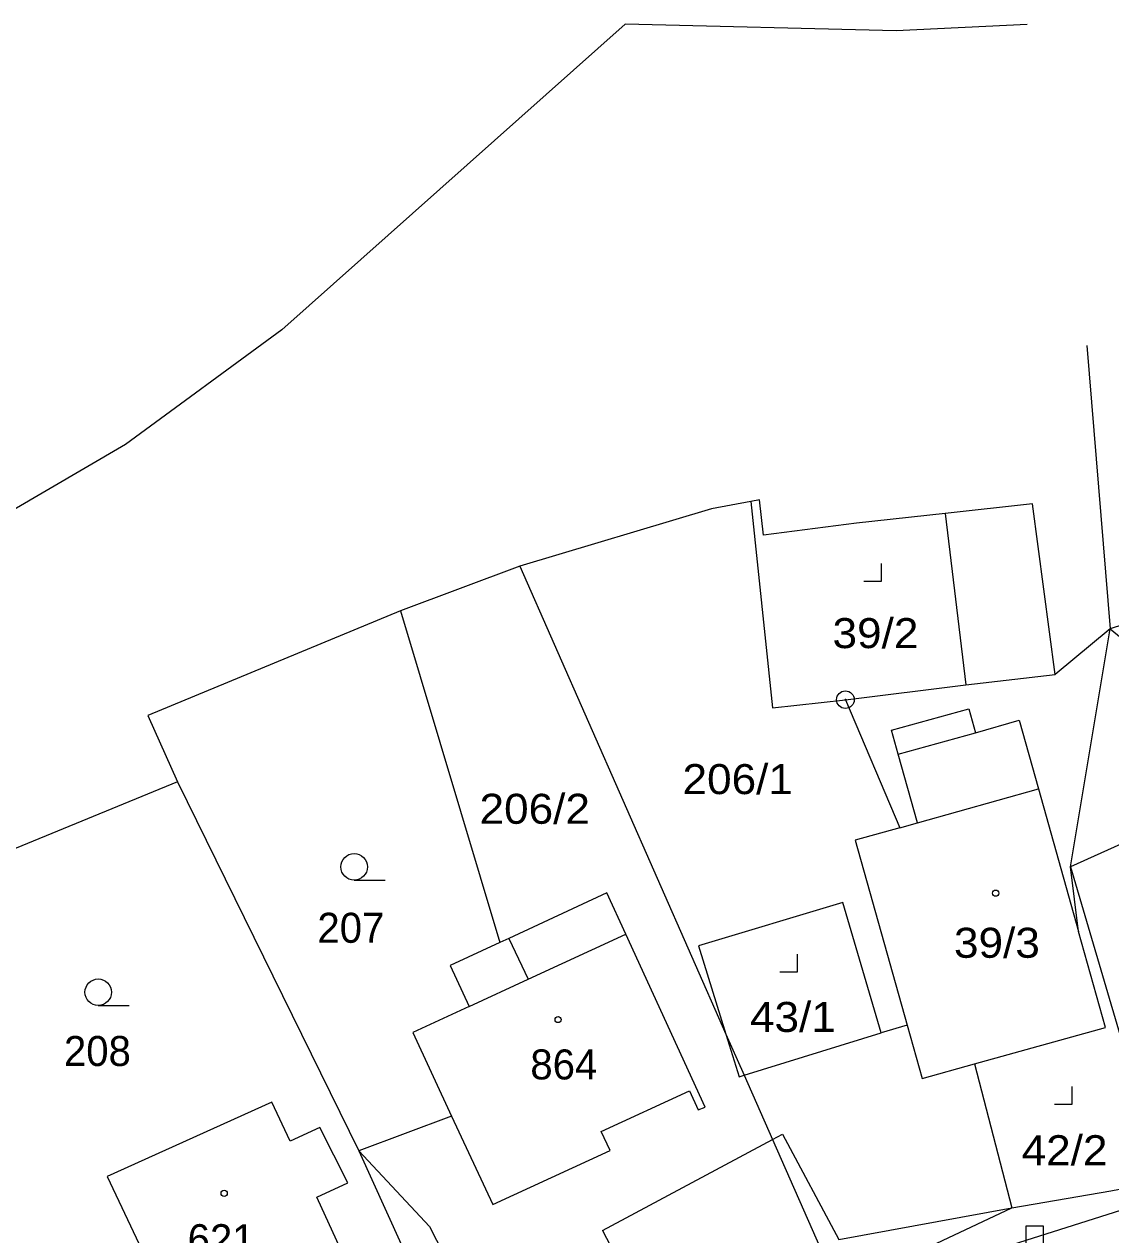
# Model space of a CAD drawing. Extents: x -686207 to -681951, y -1020493 to -1017811.
# Drawn here: x -682528.3 to -682466.7, y -1018853.5 to -1018784.9 of the extents above; entities that cross this region are included whole.
import ezdxf

# ---------------------------------------------------------------- set-up
doc = ezdxf.new("R2010")
doc.units = 0
doc.header["$LTSCALE"] = 0.4
for name, color, linetype, lineweight in [('1', 7, 'Continuous', 13), ('10', 7, 'Continuous', 13), ('3', 7, 'Continuous', 13), ('4', 7, 'Continuous', 13), ('5', 7, 'Continuous', 13), ('8', 7, 'Continuous', 13)]:
    doc.layers.add(name, color=color, linetype=linetype, lineweight=lineweight)
doc.layers.add('2', color=7, linetype='Continuous')

msp = doc.modelspace()

# ---------------------------------------------------------------- linework, layer by layer
at = {"layer": '1'}
for p, q in [((-682449.04, -1018813.56), (-682466.75, -1018819.18)), ((-682500.19, -1018815.63), (-682506.95, -1018818.17)), ((-682506.95, -1018818.17), (-682501.31, -1018836.95)), ((-682468.99, -1018832.67), (-682466.75, -1018819.18)), ((-682466.75, -1018819.18), (-682456.96, -1018827.23)), ((-682519.58, -1018827.85), (-682537.19, -1018835.09)), ((-682519.58, -1018827.85), (-682509.31, -1018848.76)), ((-682458.28, -1018827.83), (-682468.99, -1018832.67)), ((-682468.99, -1018832.67), (-682463.76, -1018850.46)), ((-682488.51, -1018842.14), (-682487.48, -1018844.47)), ((-682474.43, -1018843.83), (-682472.32, -1018851.99)), ((-682504.05, -1018846.79), (-682509.31, -1018848.76))]:
    msp.add_line(p, q, dxfattribs=at)
for points in [[(-682471.44, -1018784.95), (-682478.87, -1018785.32), (-682494.21, -1018784.94), (-682513.67, -1018802.25), (-682522.53, -1018808.75), (-682529.16, -1018812.61), (-682549.1, -1018822.73)], [(-682487.1, -1018811.97), (-682489.32, -1018812.39), (-682500.19, -1018815.63), (-682488.51, -1018842.14)], [(-682466.75, -1018819.18), (-682469.86, -1018821.78), (-682471.15, -1018812.11), (-682476.08, -1018812.65), (-682481.11, -1018813.2), (-682486.39, -1018813.89), (-682486.6, -1018811.88), (-682487.1, -1018811.97)], [(-682487.1, -1018811.97), (-682485.88, -1018823.66), (-682481.74, -1018823.2), (-682478.66, -1018830.45)], [(-682506.95, -1018818.17), (-682521.27, -1018824.1), (-682519.58, -1018827.85)], [(-682478.66, -1018830.45), (-682477.66, -1018830.17), (-682478.75, -1018826.29), (-682479.13, -1018824.93), (-682474.75, -1018823.71), (-682474.37, -1018825.07), (-682471.89, -1018824.37), (-682470.8, -1018828.25), (-682468.53, -1018836.33), (-682468.99, -1018832.67)], [(-682478.66, -1018830.45), (-682481.18, -1018831.16), (-682478.24, -1018841.63)], [(-682504.05, -1018846.79), (-682501.71, -1018851.8), (-682495.07, -1018848.74), (-682495.57, -1018847.66), (-682490.57, -1018845.36), (-682490.09, -1018846.44), (-682489.68, -1018846.28), (-682494.18, -1018836.48), (-682495.25, -1018834.15), (-682500.81, -1018836.72), (-682501.31, -1018836.95)], [(-682478.24, -1018841.63), (-682479.72, -1018842.07), (-682481.89, -1018834.69), (-682490.06, -1018837.15), (-682488.51, -1018842.14)], [(-682474.43, -1018843.83), (-682467.01, -1018841.77), (-682468.53, -1018836.33)], [(-682501.31, -1018836.95), (-682504.13, -1018838.25), (-682503.05, -1018840.58), (-682506.25, -1018842.06), (-682504.05, -1018846.79)], [(-682478.24, -1018841.63), (-682477.39, -1018844.65), (-682474.43, -1018843.83)], [(-682487.48, -1018844.47), (-682485.88, -1018848.11), (-682483.14, -1018854.32), (-682482.14, -1018856.6)], [(-682509.31, -1018848.76), (-682505.3, -1018853.04), (-682500.09, -1018863.21), (-682499.33, -1018864.69)], [(-682472.32, -1018851.99), (-682466.71, -1018851.02), (-682463.76, -1018850.46)], [(-682499.33, -1018864.69), (-682491.43, -1018860.97), (-682482.14, -1018856.6), (-682472.32, -1018851.99)]]:
    msp.add_lwpolyline(points, dxfattribs=at)
msp.add_lwpolyline([(-682514.24, -1018845.99), (-682523.57, -1018850.2), (-682519.61, -1018858.55), (-682510.35, -1018854.3), (-682511.68, -1018851.37), (-682509.93, -1018850.57), (-682511.52, -1018847.43), (-682513.19, -1018848.2)], close=True, dxfattribs=at)
at = {"layer": '10'}
msp.add_lwpolyline([(-682470.52, -1018853.03), (-682471.52, -1018853.03), (-682471.52, -1018854.03), (-682470.52, -1018854.03)], close=True, dxfattribs=at)
at = {"layer": '3'}
for p, q in [((-682509.573, -1018833.42), (-682507.823, -1018833.42)), ((-682524.073, -1018840.52), (-682522.323, -1018840.52))]:
    msp.add_line(p, q, dxfattribs=at)
for points in [[(-682480.691, -1018816.49), (-682479.69, -1018816.49), (-682479.69, -1018815.49)], [(-682485.461, -1018838.61), (-682484.46, -1018838.61), (-682484.46, -1018837.61)], [(-682469.901, -1018846.11), (-682468.9, -1018846.11), (-682468.9, -1018845.11)]]:
    msp.add_lwpolyline(points, dxfattribs=at)
for centre in [(-682509.5729, -1018832.6698), (-682524.0729, -1018839.7698)]:
    msp.add_circle(centre, 0.75, dxfattribs=at)
at = {"layer": '4'}
for p, q in [((-682468.06, -1018803.13), (-682466.75, -1018819.18)), ((-682476.08, -1018812.65), (-682474.91, -1018822.36)), ((-682474.91, -1018822.36), (-682469.86, -1018821.78)), ((-682481.74, -1018823.2), (-682474.91, -1018822.36)), ((-682478.75, -1018826.29), (-682474.37, -1018825.07)), ((-682477.66, -1018830.17), (-682470.8, -1018828.25)), ((-682503.05, -1018840.58), (-682499.71, -1018839.04)), ((-682487.48, -1018844.47), (-682479.72, -1018842.07)), ((-682482.11, -1018853.78), (-682472.32, -1018851.99)), ((-682478.44, -1018856), (-682465.73, -1018851.99)), ((-682495.5, -1018853.27), (-682492.4, -1018859.14))]:
    msp.add_line(p, q, dxfattribs=at)
for points in [[(-682500.81, -1018836.72), (-682499.71, -1018839.04), (-682494.18, -1018836.48)], [(-682488.51, -1018842.14), (-682487.76, -1018844.56), (-682487.48, -1018844.47)], [(-682495.5, -1018853.27), (-682485.88, -1018848.11), (-682485.31, -1018847.81), (-682482.11, -1018853.78)], [(-682509.31, -1018848.76), (-682502.3, -1018864.2), (-682500.09, -1018863.21)]]:
    msp.add_lwpolyline(points, dxfattribs=at)
at = {"layer": '5'}
for centre in [(-682473.2268, -1018834.1592), (-682498.0168, -1018841.3192), (-682516.9368, -1018851.1592)]:
    msp.add_circle(centre, 0.175, dxfattribs=at)
at = {"layer": '8'}
for radius in [0.5, 0.0303]:
    msp.add_circle((-682481.74, -1018823.1999), radius, dxfattribs=at)

# ---------------------------------------------------------------- texts
at = {"layer": '2', "width": 1.1}
for s, p in [('39/2', (-682482.471, -1018820.28)), ('206/1', (-682490.97, -1018828.549)), ('206/2', (-682502.47, -1018830.23)), ('39/3', (-682475.59, -1018837.82)), ('43/1', (-682487.15, -1018842.02)), ('42/2', (-682471.76, -1018849.57))]:
    msp.add_text(s, height=1.7, dxfattribs=at).set_placement(p)
at = {"layer": '2'}
for s, p in [('207', (-682511.654, -1018836.97)), ('208', (-682526.014, -1018843.95)), ('864', (-682499.59, -1018844.71)), ('621', (-682519.004, -1018854.61))]:
    msp.add_text(s, height=1.7, dxfattribs=at).set_placement(p)

doc.saveas('drawing.dxf')
